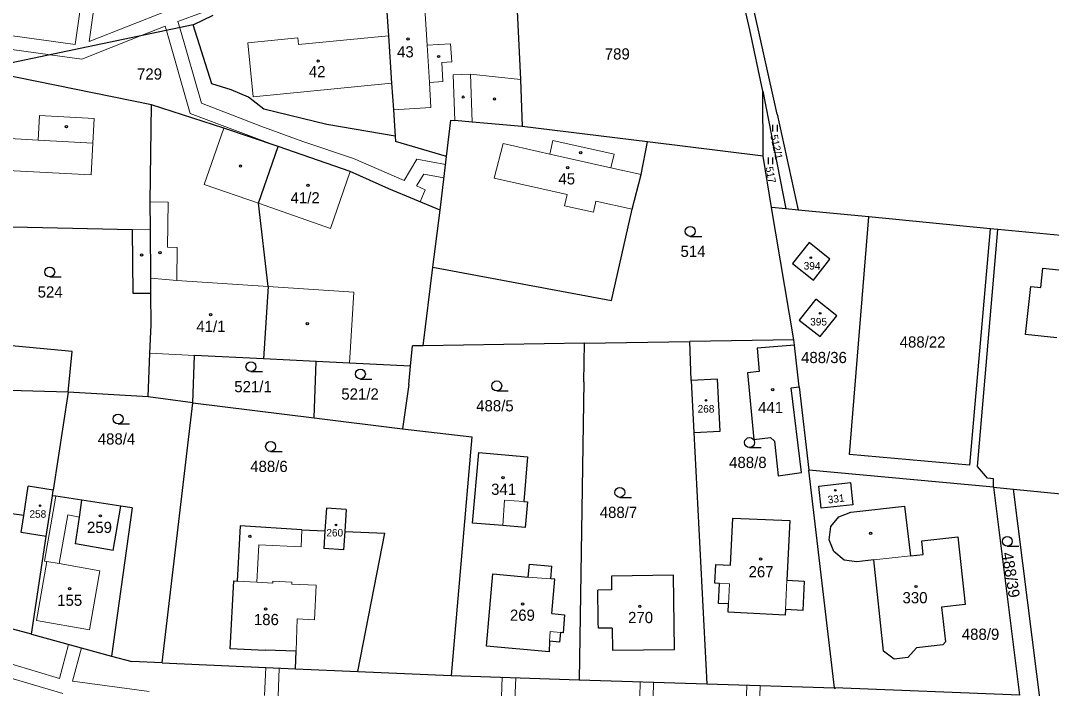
# Model space of a CAD drawing. Extents: x -701211 to -698780, y -1014269 to -1012378.
# Drawn here: x -700163.9 to -700007.4, y -1013128.7 to -1013027.3 of the extents above; entities that cross this region are included whole.
import ezdxf
from ezdxf.enums import TextEntityAlignment as Align

# ---------------------------------------------------------------- set-up
doc = ezdxf.new("R2010")
doc.units = 0
doc.header["$LTSCALE"] = 0.68
for name, color, linetype, lineweight in [('1', 7, 'Continuous', 25), ('13', 7, 'Continuous', 13), ('3', 7, 'Continuous', 25), ('4', 7, 'Continuous', 13), ('5', 7, 'Continuous', 25)]:
    doc.layers.add(name, color=color, linetype=linetype, lineweight=lineweight)
doc.layers.add('2', color=7, linetype='Continuous')

msp = doc.modelspace()

# ---------------------------------------------------------------- linework, layer by layer
at = {"layer": '1'}
for p, q in [((-700108.9, -1013017.28), (-700108.08, -1013029.61)), ((-700088.72, -1013021.67), (-700088.04, -1013036.26)), ((-700049.09, -1013041.5), (-700053.24, -1013022.73)), ((-700053.2, -1013028.72), (-700054.12, -1013024.75)), ((-700137.73, -1013027.96), (-700134.7, -1013026.48)), ((-700137.73, -1013027.96), (-700170.3, -1013034.75)), ((-700134.87, -1013036.88), (-700137.73, -1013027.96)), ((-700051.22, -1013037.99), (-700053.2, -1013028.72)), ((-700108.08, -1013029.61), (-700107.6, -1013036.8)), ((-700144.05, -1013040.07), (-700170.3, -1013034.75)), ((-700088.04, -1013036.26), (-700087.76, -1013043.36)), ((-700131.96, -1013037.79), (-700134.87, -1013036.88)), ((-700129.33, -1013038.9), (-700131.96, -1013037.79)), ((-700107.6, -1013036.8), (-700107.33, -1013040.87)), ((-700051.22, -1013037.99), (-700047.74, -1013055.89)), ((-700051.21, -1013047.88), (-700051.22, -1013037.99)), ((-700126.98, -1013040.74), (-700129.33, -1013038.9)), ((-700144.24, -1013054.83), (-700144.05, -1013040.07)), ((-700133.05, -1013043.63), (-700144.05, -1013040.07)), ((-700117.42, -1013043.06), (-700126.98, -1013040.74)), ((-700107.33, -1013040.87), (-700107.07, -1013044.86)), ((-700099.26, -1013047.93), (-700098.59, -1013042.42)), ((-700098.59, -1013042.42), (-700098.01, -1013042.47)), ((-700095.38, -1013042.7), (-700098.01, -1013042.47)), ((-700087.76, -1013043.36), (-700095.38, -1013042.7)), ((-700049.09, -1013041.5), (-700045.89, -1013056.07)), ((-700124.81, -1013046.42), (-700133.05, -1013043.63)), ((-700107.07, -1013044.86), (-700117.42, -1013043.06)), ((-700068.74, -1013045.71), (-700087.76, -1013043.36)), ((-700107.07, -1013044.86), (-700107.02, -1013045.66)), ((-700099.26, -1013047.93), (-700107.02, -1013045.66)), ((-700069.71, -1013050.66), (-700068.74, -1013045.71)), ((-700051.21, -1013047.88), (-700068.74, -1013045.71)), ((-700127.82, -1013055.03), (-700124.81, -1013046.42)), ((-700113.91, -1013050.2), (-700124.81, -1013046.42)), ((-700100.25, -1013056.07), (-700099.26, -1013047.93)), ((-700049.91, -1013055.68), (-700051.21, -1013047.88)), ((-700108, -1013052.85), (-700113.91, -1013050.2)), ((-700071.06, -1013055.94), (-700069.71, -1013050.66)), ((-700100.25, -1013056.07), (-700108, -1013052.85)), ((-700144.21, -1013059.02), (-700144.24, -1013054.83)), ((-700126.36, -1013067.66), (-700127.82, -1013055.03)), ((-700101.33, -1013064.72), (-700100.25, -1013056.07)), ((-700074.2, -1013069.8), (-700071.06, -1013055.94)), ((-700047.74, -1013055.89), (-700049.91, -1013055.68)), ((-700046.55, -1013075.76), (-700049.91, -1013055.68)), ((-700045.89, -1013056.07), (-700047.74, -1013055.89)), ((-700035.17, -1013057.11), (-700045.89, -1013056.07)), ((-700146.91, -1013059.04), (-700172.23, -1013058.52)), ((-700038.1, -1013093.17), (-700035.17, -1013057.11)), ((-700016.74, -1013058.9), (-700035.17, -1013057.11)), ((-700146.83, -1013068.74), (-700146.91, -1013059.04)), ((-700144.15, -1013066.4), (-700144.21, -1013059.02)), ((-700016.74, -1013058.9), (-700019.86, -1013094.8)), ((-700018.65, -1013094.98), (-700015.56, -1013059.01)), ((-700015.56, -1013059.01), (-700016.74, -1013058.9)), ((-699986.24, -1013061.84), (-700015.56, -1013059.01)), ((-700044.21, -1013060.98), (-700046.74, -1013064.15)), ((-700041.05, -1013063.5), (-700044.21, -1013060.98)), ((-700102.81, -1013076.65), (-700101.33, -1013064.72)), ((-700101.33, -1013064.72), (-700074.2, -1013069.8)), ((-700046.74, -1013064.15), (-700043.57, -1013066.68)), ((-700043.57, -1013066.68), (-700041.05, -1013063.5)), ((-700144.13, -1013068.72), (-700144.15, -1013066.4)), ((-700009.03, -1013067.82), (-700008.72, -1013064.88)), ((-700008.72, -1013064.88), (-699989.01, -1013067)), ((-700126.36, -1013067.66), (-700127.05, -1013078.65)), ((-700011.35, -1013074.95), (-700010.56, -1013067.65)), ((-700010.56, -1013067.65), (-700009.03, -1013067.82)), ((-700144.13, -1013068.72), (-700146.83, -1013068.74)), ((-700144.1, -1013073.5), (-700144.13, -1013068.72)), ((-700043.21, -1013069.59), (-700045.72, -1013072.77)), ((-700040.03, -1013072.1), (-700043.21, -1013069.59)), ((-700042.54, -1013075.27), (-700040.03, -1013072.1)), ((-700144.28, -1013077.8), (-700144.1, -1013073.5)), ((-700045.72, -1013072.77), (-700042.54, -1013075.27)), ((-700046.55, -1013075.76), (-700062.35, -1013076.01)), ((-700046.46, -1013076.57), (-700046.55, -1013075.76)), ((-700006.63, -1013075.46), (-700011.35, -1013074.95)), ((-700156.09, -1013077.52), (-700174.85, -1013075.81)), ((-700104.72, -1013079.76), (-700104.42, -1013076.68)), ((-700102.81, -1013076.65), (-700104.42, -1013076.68)), ((-700078.31, -1013076.26), (-700102.81, -1013076.65)), ((-700078.43, -1013082.14), (-700078.31, -1013076.26)), ((-700078.31, -1013076.26), (-700062.35, -1013076.01)), ((-700062.14, -1013081.92), (-700062.35, -1013076.01)), ((-700046.46, -1013076.57), (-700052.13, -1013077.03)), ((-700052.13, -1013077.03), (-700051.81, -1013080.59)), ((-700045.73, -1013082.89), (-700046.46, -1013076.57)), ((-700156.72, -1013083.73), (-700156.09, -1013077.52)), ((-700144.55, -1013084.4), (-700144.28, -1013077.8)), ((-700137.77, -1013085.33), (-700137.5, -1013078.13)), ((-700127.05, -1013078.65), (-700137.5, -1013078.13)), ((-700119.04, -1013079.05), (-700127.05, -1013078.65)), ((-700119.36, -1013087.6), (-700119.04, -1013079.05)), ((-700114.01, -1013079.3), (-700119.04, -1013079.05)), ((-700104.72, -1013079.76), (-700114.01, -1013079.3)), ((-700104.99, -1013082.53), (-700104.72, -1013079.76)), ((-700058.14, -1013081.71), (-700062.14, -1013081.92)), ((-700057.73, -1013089.63), (-700058.14, -1013081.71)), ((-700051.81, -1013080.59), (-700053.57, -1013080.77)), ((-700053.57, -1013080.77), (-700052.61, -1013090.89)), ((-700156.72, -1013083.73), (-700177.15, -1013083.11)), ((-700104.99, -1013082.53), (-700105.94, -1013089.25)), ((-700078.43, -1013082.14), (-700079.15, -1013127.36)), ((-700045.36, -1013095.92), (-700046.94, -1013083.07)), ((-700156.72, -1013083.73), (-700158.97, -1013098.58)), ((-700144.55, -1013084.4), (-700156.72, -1013083.73)), ((-700137.77, -1013085.33), (-700144.55, -1013084.4)), ((-700142.44, -1013124.81), (-700137.77, -1013085.33)), ((-700137.77, -1013085.33), (-700119.36, -1013087.6)), ((-700119.36, -1013087.6), (-700105.94, -1013089.25)), ((-700105.94, -1013089.25), (-700095.42, -1013090.47)), ((-700061.73, -1013089.84), (-700059.76, -1013127.98)), ((-700095.42, -1013090.47), (-700098.56, -1013126.74)), ((-700052.61, -1013090.89), (-700050.1, -1013090.61)), ((-700050.1, -1013090.61), (-700049.45, -1013091.16)), ((-700049.45, -1013091.16), (-700048.93, -1013096.4)), ((-700095.3, -1013103.61), (-700094.37, -1013092.88)), ((-700094.37, -1013092.88), (-700086.97, -1013093.5)), ((-700086.97, -1013093.5), (-700087.52, -1013100.31)), ((-700019.86, -1013094.8), (-700038.1, -1013093.17)), ((-700048.93, -1013096.4), (-700045.36, -1013095.92)), ((-700040.36, -1013128.6), (-700044.25, -1013095.53)), ((-700016.24, -1013098.13), (-700044.25, -1013095.53)), ((-700017.14, -1013096.78), (-700018.65, -1013094.98)), ((-700042.75, -1013097.97), (-700037.92, -1013097.42)), ((-700037.92, -1013097.42), (-700037.59, -1013100.79)), ((-700016.22, -1013096.87), (-700017.14, -1013096.78)), ((-700016.24, -1013098.13), (-700016.22, -1013096.87)), ((-700163.44, -1013102.42), (-700162.76, -1013098)), ((-700158.97, -1013098.58), (-700162.76, -1013098)), ((-700159.1, -1013099.42), (-700158.97, -1013098.58)), ((-700042.39, -1013101.33), (-700042.75, -1013097.97)), ((-700016.24, -1013098.13), (-700013.18, -1013098.42)), ((-700016.24, -1013098.13), (-700012.28, -1013129.72)), ((-700013.18, -1013098.42), (-699981.39, -1013101.55)), ((-700008.94, -1013132.15), (-700013.18, -1013098.42)), ((-700163.44, -1013102.42), (-700180.99, -1013100.06)), ((-700160.05, -1013105.61), (-700159.1, -1013099.42)), ((-700158.56, -1013099.5), (-700159.1, -1013099.42)), ((-700154.63, -1013100.11), (-700158.56, -1013099.5)), ((-700155, -1013102.66), (-700154.63, -1013100.11)), ((-700148.7, -1013101.03), (-700154.63, -1013100.11)), ((-700087.52, -1013100.31), (-700086.96, -1013100.34)), ((-700086.96, -1013100.34), (-700087.3, -1013104.24)), ((-700037.59, -1013100.79), (-700042.39, -1013101.33)), ((-700147, -1013101.29), (-700150.12, -1013123.78)), ((-700149.87, -1013107.73), (-700148.7, -1013101.03)), ((-700147, -1013101.29), (-700148.7, -1013101.03)), ((-700117.49, -1013101.31), (-700117.71, -1013104.74)), ((-700114.5, -1013101.5), (-700117.49, -1013101.31)), ((-700114.5, -1013101.5), (-700114.71, -1013104.87)), ((-700039.69, -1013102.61), (-700037.89, -1013101.92)), ((-700037.89, -1013101.92), (-700029.73, -1013101)), ((-700029.73, -1013101), (-700028.84, -1013108.56)), ((-700163.84, -1013105.03), (-700163.44, -1013102.42)), ((-700155.6, -1013106.73), (-700155, -1013102.66)), ((-700090.73, -1013103.97), (-700095.3, -1013103.61)), ((-700056.14, -1013109.99), (-700055.81, -1013102.83)), ((-700055.81, -1013102.83), (-700047.14, -1013103.19)), ((-700047.14, -1013103.19), (-700047.59, -1013112.27)), ((-700040.93, -1013104.08), (-700039.69, -1013102.61)), ((-700160.05, -1013105.61), (-700163.84, -1013105.03)), ((-700130.58, -1013104), (-700131.03, -1013112.39)), ((-700121.24, -1013104.59), (-700130.58, -1013104)), ((-700121.24, -1013104.59), (-700117.71, -1013104.74)), ((-700117.71, -1013104.74), (-700117.88, -1013107.45)), ((-700114.71, -1013104.87), (-700114.89, -1013107.64)), ((-700114.71, -1013104.87), (-700108.65, -1013105.12)), ((-700112.7, -1013126.12), (-700108.65, -1013105.12)), ((-700087.3, -1013104.24), (-700090.73, -1013103.97)), ((-700041.16, -1013106.15), (-700040.93, -1013104.08)), ((-700162.25, -1013120.45), (-700160.05, -1013105.61)), ((-700149.87, -1013107.73), (-700155.6, -1013106.73)), ((-700040.45, -1013107.9), (-700041.16, -1013106.15)), ((-700027.12, -1013106.27), (-700021.65, -1013105.68)), ((-700026.89, -1013108.34), (-700027.12, -1013106.27)), ((-700021.65, -1013105.68), (-700020.54, -1013115.94)), ((-700114.89, -1013107.64), (-700117.88, -1013107.45)), ((-700038.91, -1013109.23), (-700040.45, -1013107.9)), ((-700028.84, -1013108.56), (-700026.89, -1013108.34)), ((-700086.85, -1013111.77), (-700086.68, -1013109.81)), ((-700086.68, -1013109.81), (-700083.27, -1013110.1)), ((-700083.43, -1013112.06), (-700083.27, -1013110.1)), ((-700058.51, -1013112.71), (-700058.37, -1013109.88)), ((-700058.37, -1013109.88), (-700056.14, -1013109.99)), ((-700036.96, -1013109.47), (-700038.91, -1013109.23)), ((-700034.41, -1013109.18), (-700036.96, -1013109.47)), ((-700032.92, -1013123.05), (-700034.41, -1013109.18)), ((-700093.19, -1013122.29), (-700092.22, -1013111.31)), ((-700092.22, -1013111.31), (-700086.85, -1013111.77)), ((-700064.83, -1013111.49), (-700074.23, -1013111.63)), ((-700074.23, -1013111.63), (-700074.2, -1013113.73)), ((-700064.64, -1013122.76), (-700064.83, -1013111.49)), ((-700132.08, -1013122.65), (-700131.53, -1013112.36)), ((-700131.53, -1013112.36), (-700131.03, -1013112.39)), ((-700082.84, -1013112.12), (-700083.43, -1013112.06)), ((-700083.29, -1013117.33), (-700082.84, -1013112.12)), ((-700057.81, -1013112.74), (-700058.51, -1013112.71)), ((-700057.96, -1013115.78), (-700057.81, -1013112.74)), ((-700047.59, -1013112.27), (-700044.95, -1013112.4)), ((-700044.95, -1013112.4), (-700045.17, -1013116.84)), ((-700074.2, -1013113.73), (-700076.3, -1013113.78)), ((-700076.23, -1013118.22), (-700076.3, -1013113.78)), ((-700056.47, -1013115.86), (-700057.96, -1013115.78)), ((-700056.53, -1013117.12), (-700056.47, -1013115.86)), ((-700020.54, -1013115.94), (-700024.11, -1013116.33)), ((-700024.11, -1013116.33), (-700023.54, -1013121.59)), ((-700083.29, -1013117.33), (-700081.34, -1013117.52)), ((-700081.34, -1013117.52), (-700081.53, -1013120.24)), ((-700047.85, -1013117.55), (-700056.53, -1013117.12)), ((-700047.81, -1013116.71), (-700047.85, -1013117.55)), ((-700045.17, -1013116.84), (-700047.81, -1013116.71)), ((-700076.23, -1013118.71), (-700076.23, -1013118.22)), ((-700076.21, -1013119.56), (-700076.23, -1013118.71)), ((-700074.12, -1013119.53), (-700076.21, -1013119.56)), ((-700074.12, -1013119.53), (-700074.08, -1013122.87)), ((-700162.25, -1013120.45), (-700150.12, -1013123.78)), ((-700081.98, -1013120.17), (-700082.1, -1013121.64)), ((-700081.53, -1013120.24), (-700081.98, -1013120.17)), ((-700126.79, -1013122.93), (-700132.08, -1013122.65)), ((-700083.69, -1013123.15), (-700093.19, -1013122.29)), ((-700083.65, -1013121.51), (-700083.69, -1013123.15)), ((-700082.1, -1013121.64), (-700083.65, -1013121.51)), ((-700027.92, -1013122.52), (-700029.25, -1013124)), ((-700023.93, -1013122.09), (-700027.92, -1013122.52)), ((-700023.54, -1013121.59), (-700023.93, -1013122.09)), ((-700150.12, -1013123.78), (-700147.04, -1013124.62)), ((-700126.79, -1013122.93), (-700126.79, -1013122.83)), ((-700126.79, -1013122.83), (-700122.09, -1013123)), ((-700122.19, -1013125.7), (-700122.09, -1013123)), ((-700074.08, -1013122.87), (-700064.64, -1013122.76)), ((-700031.3, -1013124.23), (-700032.92, -1013123.05)), ((-700029.25, -1013124), (-700031.3, -1013124.23)), ((-700142.44, -1013124.81), (-700147.04, -1013124.62)), ((-700142.44, -1013124.81), (-700122.19, -1013125.7)), ((-700122.19, -1013125.7), (-700112.7, -1013126.12)), ((-700112.7, -1013126.12), (-700098.56, -1013126.74)), ((-700098.56, -1013126.74), (-700079.15, -1013127.36)), ((-700079.15, -1013127.36), (-700059.76, -1013127.98)), ((-700059.76, -1013127.98), (-700040.36, -1013128.6)), ((-700012.28, -1013129.72), (-700040.36, -1013128.6)), ((-700040.36, -1013128.6), (-700040.34, -1013128.77))]:
    msp.add_line(p, q, dxfattribs=at)
for points in [[(-700062.14, -1013081.92), (-700061.73, -1013089.84), (-700057.73, -1013089.63)], [(-700046.94, -1013083.07), (-700045.73, -1013082.89), (-700044.25, -1013095.53)], [(-700162.25, -1013120.45), (-700181.66, -1013115.29), (-700203.69, -1013106.81)]]:
    msp.add_lwpolyline(points, dxfattribs=at)
at = {"layer": '13'}
for points in [[(-700177.66, -1013029.98), (-700159.43, -1013032.48), (-700154.64, -1013033.14), (-700145.72, -1013029.63), (-700141.98, -1013028.15), (-700141.79, -1013028.81), (-700138.16, -1013041.39), (-700124.81, -1013046.42), (-700113.91, -1013050.2), (-700108, -1013052.85), (-700103.27, -1013054.81), (-700102.48, -1013052.98), (-700103.81, -1013052.4), (-700102.73, -1013050.6), (-700099.65, -1013051.18), (-700099.41, -1013049.15), (-700103.75, -1013048.34), (-700105.69, -1013051.58), (-700113.37, -1013048.25), (-700121.06, -1013045.63), (-700127.43, -1013043.3), (-700136.46, -1013039.83), (-700139.77, -1013028.39), (-700140.05, -1013027.41), (-700122.09, -1013020.82)], [(-700154.53, -1013023.08), (-700155.63, -1013030.93), (-700178.36, -1013027.8)], [(-700141.68, -1013025.81), (-700153.51, -1013030.48), (-700152.91, -1013026.19)], [(-700144.38, -1013129.15), (-700156.02, -1013127.59), (-700154.68, -1013122.53), (-700156.64, -1013121.99), (-700158.01, -1013127.17), (-700169.16, -1013123.85)], [(-700124.84, -1013129.92), (-700124.65, -1013125.59), (-700126.69, -1013125.5), (-700126.87, -1013129.78)], [(-700168.67, -1013126.14), (-700157.52, -1013129.47)], [(-700088.93, -1013131.65), (-700088.76, -1013127.05), (-700090.79, -1013126.99), (-700090.96, -1013131.49)], [(-700067.94, -1013132.42), (-700067.82, -1013127.72), (-700069.85, -1013127.66), (-700069.97, -1013132.36)], [(-700051.78, -1013132.98), (-700051.63, -1013128.24), (-700053.66, -1013128.18), (-700053.81, -1013132.9)]]:
    msp.add_lwpolyline(points, dxfattribs=at)
at = {"layer": '3'}
for p, q in [((-700049.702, -1013044.15), (-700049.702, -1013043.145)), ((-700049.032, -1013044.15), (-700049.032, -1013043.145)), ((-700050.372, -1013049.09), (-700050.372, -1013048.085)), ((-700049.702, -1013049.09), (-700049.702, -1013048.085)), ((-700062.273, -1013060.05), (-700060.523, -1013060.05)), ((-700159.493, -1013066.22), (-700157.743, -1013066.22)), ((-700128.953, -1013080.59), (-700127.203, -1013080.59)), ((-700112.333, -1013081.71), (-700110.583, -1013081.71)), ((-700091.633, -1013083.5), (-700089.883, -1013083.5)), ((-700149.113, -1013088.53), (-700147.363, -1013088.53)), ((-700125.973, -1013092.7), (-700124.223, -1013092.7)), ((-700053.263, -1013092.1), (-700051.513, -1013092.1)), ((-700072.953, -1013099.68), (-700071.203, -1013099.68)), ((-700014.133, -1013107.11), (-700012.383, -1013107.11))]:
    msp.add_line(p, q, dxfattribs=at)
for centre in [(-700062.2729, -1013059.2998), (-700159.4929, -1013065.4698), (-700128.9529, -1013079.8398), (-700112.3329, -1013080.9598), (-700091.6329, -1013082.7498), (-700149.1129, -1013087.7798), (-700125.9729, -1013091.9498), (-700053.2629, -1013091.3498), (-700072.9529, -1013098.9298), (-700014.1329, -1013106.3598)]:
    msp.add_circle(centre, 0.75, dxfattribs=at)
at = {"layer": '4'}
for p, q in [((-700102.21, -1013031.03), (-700103.17, -1013015.81)), ((-700121.81, -1013029.93), (-700129.41, -1013030.67)), ((-700121.71, -1013030.94), (-700121.81, -1013029.93)), ((-700108.08, -1013029.61), (-700121.71, -1013030.94)), ((-700128.61, -1013038.85), (-700129.41, -1013030.67)), ((-700102.21, -1013031.03), (-700098.65, -1013030.8)), ((-700101.86, -1013036.67), (-700102.21, -1013031.03)), ((-700098.65, -1013030.8), (-700098.48, -1013033.55)), ((-700098.48, -1013033.55), (-700099.99, -1013033.65)), ((-700099.99, -1013033.65), (-700099.81, -1013036.54)), ((-700099.81, -1013036.54), (-700101.86, -1013036.67)), ((-700101.86, -1013036.67), (-700101.62, -1013040.51)), ((-700098.24, -1013035.54), (-700095.62, -1013035.45)), ((-700098.01, -1013042.47), (-700098.24, -1013035.54)), ((-700095.38, -1013042.7), (-700095.62, -1013035.45)), ((-700095.62, -1013035.45), (-700088.04, -1013036.26)), ((-700107.6, -1013036.8), (-700128.61, -1013038.85)), ((-700107.33, -1013040.87), (-700101.62, -1013040.51)), ((-700161.05, -1013041.69), (-700161.25, -1013045.44)), ((-700161.05, -1013041.69), (-700152.76, -1013042.14)), ((-700152.96, -1013045.88), (-700152.76, -1013042.14)), ((-700136.04, -1013052.17), (-700133.05, -1013043.63)), ((-700161.25, -1013045.44), (-700174.2, -1013044.74)), ((-700161.25, -1013045.44), (-700152.96, -1013045.88)), ((-700153.22, -1013050.73), (-700152.96, -1013045.88)), ((-700090.66, -1013045.95), (-700092.01, -1013051.23)), ((-700090.66, -1013045.95), (-700083.56, -1013047.55)), ((-700083.1, -1013045.49), (-700083.56, -1013047.55)), ((-700083.1, -1013045.49), (-700073.83, -1013047.58)), ((-700074.3, -1013049.63), (-700073.83, -1013047.58)), ((-700113.91, -1013050.2), (-700116.89, -1013058.84)), ((-700127.82, -1013055.03), (-700136.04, -1013052.17)), ((-700092.01, -1013051.23), (-700080.96, -1013053.72)), ((-700081.33, -1013055.4), (-700080.96, -1013053.72)), ((-700116.89, -1013058.84), (-700127.82, -1013055.03)), ((-700076.97, -1013056.37), (-700081.33, -1013055.4)), ((-700076.97, -1013056.37), (-700076.6, -1013054.7)), ((-700076.6, -1013054.7), (-700071.06, -1013055.94)), ((-700144.21, -1013059.02), (-700146.91, -1013059.04)), ((-700141.63, -1013061.71), (-700140.13, -1013061.73)), ((-700140.19, -1013066.73), (-700140.13, -1013061.73)), ((-700144.15, -1013066.4), (-700140.19, -1013066.73)), ((-700126.36, -1013067.66), (-700140.19, -1013066.73)), ((-700137.5, -1013078.13), (-700144.28, -1013077.8)), ((-700158.56, -1013099.5), (-700160.27, -1013109.35)), ((-700090.73, -1013103.97), (-700090.45, -1013100.1)), ((-700090.45, -1013100.1), (-700087.52, -1013100.31)), ((-700158.05, -1013109.74), (-700156.77, -1013102.35)), ((-700156.77, -1013102.35), (-700155, -1013102.66)), ((-700121.35, -1013107.19), (-700121.24, -1013104.59)), ((-700128.04, -1013112.55), (-700127.73, -1013106.86)), ((-700127.73, -1013106.86), (-700121.35, -1013107.19)), ((-700034.41, -1013109.18), (-700028.84, -1013108.56)), ((-700161.49, -1013118.38), (-700159.93, -1013109.41)), ((-700159.93, -1013109.41), (-700160.27, -1013109.35)), ((-700158.05, -1013109.74), (-700159.93, -1013109.41)), ((-700151.9, -1013110.81), (-700158.05, -1013109.74)), ((-700153.46, -1013119.78), (-700151.9, -1013110.81)), ((-700086.85, -1013111.77), (-700083.43, -1013112.06)), ((-700128.04, -1013112.55), (-700131.03, -1013112.39)), ((-700125.64, -1013112.68), (-700128.04, -1013112.55)), ((-700122.73, -1013112.53), (-700122.75, -1013112.83)), ((-700119.05, -1013113.03), (-700122.75, -1013112.83)), ((-700119.32, -1013118.25), (-700119.05, -1013113.03)), ((-700057.81, -1013112.74), (-700056.3, -1013112.81)), ((-700056.3, -1013112.81), (-700056.47, -1013115.86)), ((-700047.81, -1013116.71), (-700047.59, -1013112.27)), ((-700153.46, -1013119.78), (-700161.49, -1013118.38)), ((-700122.09, -1013123), (-700121.92, -1013118.12)), ((-700119.32, -1013118.25), (-700121.92, -1013118.12))]:
    msp.add_line(p, q, dxfattribs=at)
for points in [[(-700083.56, -1013047.55), (-700074.3, -1013049.63), (-700069.71, -1013050.66)], [(-700174.3, -1013049.59), (-700171.76, -1013049.73), (-700153.22, -1013050.73)], [(-700141.63, -1013061.71), (-700141.54, -1013054.86), (-700144.24, -1013054.83)], [(-700126.36, -1013067.66), (-700113.31, -1013068.54), (-700114.01, -1013079.3)], [(-700122.73, -1013112.53), (-700125.62, -1013112.38), (-700125.64, -1013112.68)], [(-700081.98, -1013120.17), (-700083.52, -1013120.04), (-700083.65, -1013121.51)]]:
    msp.add_lwpolyline(points, dxfattribs=at)
at = {"layer": '5'}
for centre, radius in [((-700105.0868, -1013030.0692), 0.175), ((-700118.7468, -1013033.4492), 0.175), ((-700100.4668, -1013032.7492), 0.175), ((-700096.7368, -1013038.9192), 0.175), ((-700091.9768, -1013039.1992), 0.175), ((-700156.9668, -1013043.3792), 0.175), ((-700078.8868, -1013047.3692), 0.175), ((-700130.5368, -1013049.3892), 0.175), ((-700080.8568, -1013049.6092), 0.175), ((-700120.2968, -1013052.2892), 0.175), ((-700145.5468, -1013062.8692), 0.175), ((-700142.7768, -1013062.5292), 0.175), ((-700043.9646, -1013063.2894), 0.1172), ((-700135.0668, -1013071.9592), 0.175), ((-700042.5446, -1013071.7294), 0.1172), ((-700120.3968, -1013073.3192), 0.175), ((-700049.7368, -1013083.3092), 0.175), ((-700059.8746, -1013084.9594), 0.1172), ((-700090.6668, -1013096.6992), 0.175), ((-700040.2446, -1013098.6094), 0.1172), ((-700160.9546, -1013100.9494), 0.1172), ((-700151.8068, -1013102.4792), 0.175), ((-700116.0446, -1013103.8594), 0.1172), ((-700129.1168, -1013105.5792), 0.175), ((-700034.8868, -1013105.1192), 0.175), ((-700051.5768, -1013109.0292), 0.175), ((-700027.9868, -1013113.2092), 0.175), ((-700156.4868, -1013113.5292), 0.175), ((-700126.7168, -1013116.6092), 0.175), ((-700087.7068, -1013115.8492), 0.175), ((-700069.9168, -1013116.2192), 0.175)]:
    msp.add_circle(centre, radius, dxfattribs=at)

# ---------------------------------------------------------------- texts
at = {"layer": '2'}
for s, p in [('43', (-700106.77, -1013032.885)), ('729', (-700146.24, -1013036.255)), ('42', (-700120.16, -1013035.895)), ('45', (-700082.27, -1013052.165)), ('41/2', (-700122.93, -1013055.045)), ('514', (-700063.74, -1013063.175)), ('524', (-700161.33, -1013069.345)), ('41/1', (-700137.24, -1013074.575)), ('488/22', (-700030.47, -1013076.935)), ('488/36', (-700045.44, -1013079.295)), ('521/1', (-700131.48, -1013083.715)), ('521/2', (-700115.23, -1013084.835)), ('488/5', (-700094.76, -1013086.625)), ('488/4', (-700152.2, -1013091.655)), ('488/6', (-700129.06, -1013095.825)), ('488/8', (-700056.36, -1013095.225)), ('341', (-700092.49, -1013099.295)), ('488/7', (-700076, -1013102.805)), ('259', (-700153.84, -1013105.085)), ('267', (-700053.41, -1013111.815)), ('155', (-700158.36, -1013116.145)), ('330', (-700030.04, -1013115.755)), ('186', (-700128.5, -1013119.075)), ('269', (-700089.64, -1013118.415)), ('270', (-700071.7, -1013118.765)), ('488/9', (-700021.04, -1013121.305))]:
    msp.add_text(s, height=1.7, dxfattribs=at).set_placement(p)
for s, height, p in [('789', 1.7, (-700073.339, -1013033.205)), ('394', 1.14, (-700043.77, -1013065.095)), ('395', 1.14, (-700042.78, -1013073.585)), ('268', 1.14, (-700059.87, -1013086.805)), ('441', 1.7, (-700050.069, -1013086.895)), ('258', 1.14, (-700161.3, -1013102.775)), ('260', 1.14, (-700116.23, -1013105.615))]:
    msp.add_text(s, height=height, dxfattribs=at).set_placement(p, align=Align.CENTER)
for s, rotation, p in [('512/1', 282, (-700049.7257, -1013046.599)), ('517', 281, (-700050.5983, -1013050.8292)), ('331', 7, (-700040.049, -1013100.4581))]:
    msp.add_text(s, height=1.14, rotation=rotation, dxfattribs=at).set_placement(p, align=Align.CENTER)
msp.add_text('488/39', height=1.7, rotation=279, dxfattribs=at).set_placement((-700014.969, -1013108.146))

doc.saveas('drawing.dxf')
